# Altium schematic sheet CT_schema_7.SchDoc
size 391 x 238 mm
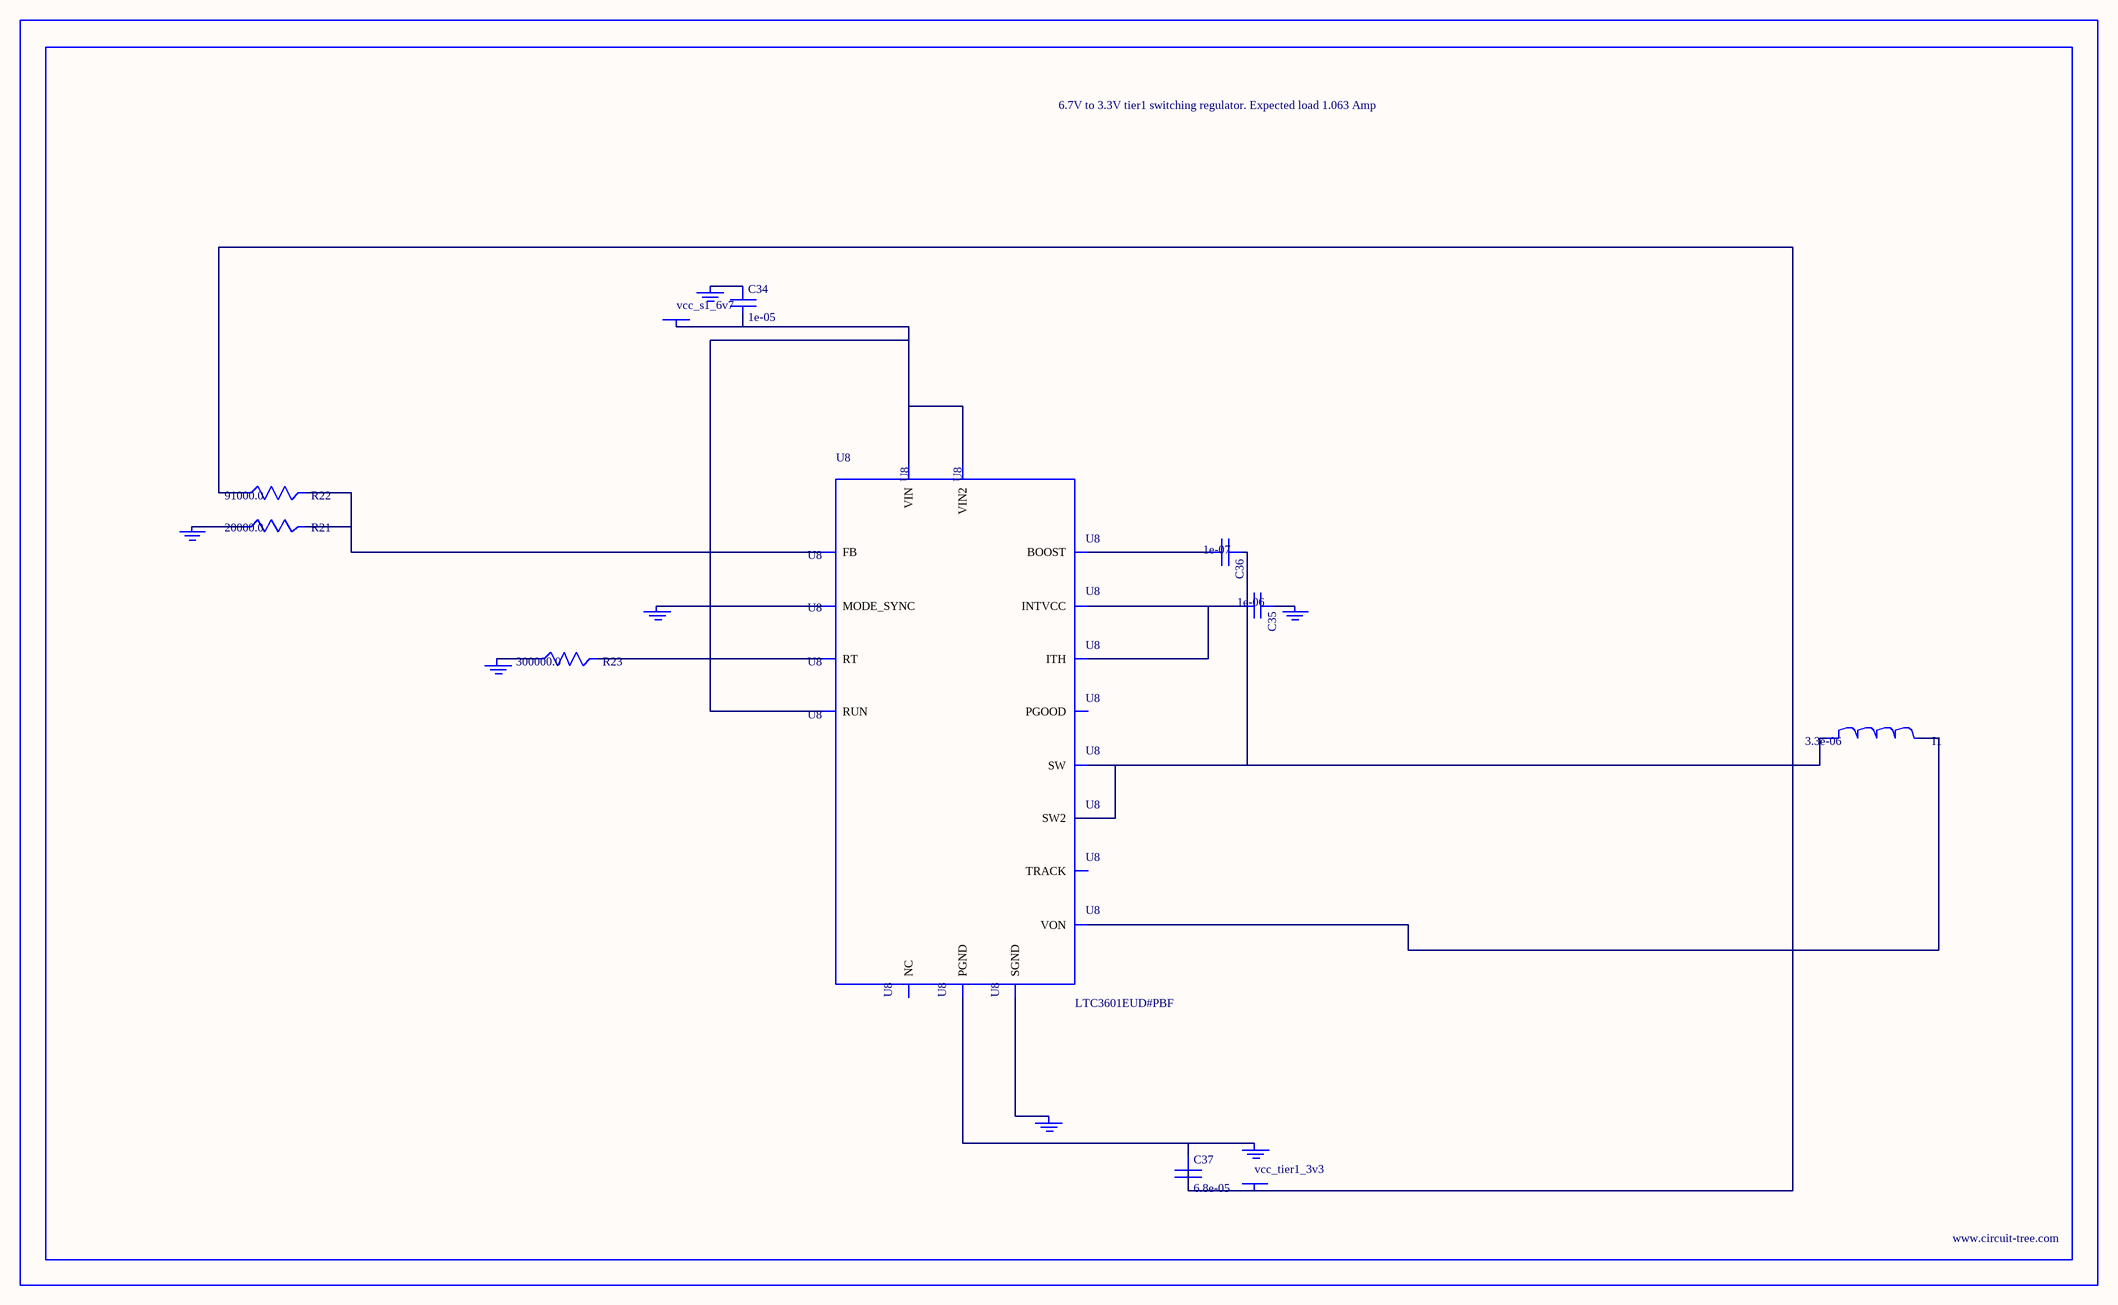
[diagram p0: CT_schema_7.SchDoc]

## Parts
BORDER6  (no value)
C34  1e-05  [C0805]
C35  1e-06  [C0603]
C36  1e-07  [C0402]
C37  6.8e-05  [2220]
GND_INSTANCE_6_0  (no value)
GND_INSTANCE_6_1  (no value)
GND_INSTANCE_6_2  (no value)
GND_INSTANCE_6_3  (no value)
GND_INSTANCE_6_4  (no value)
GND_INSTANCE_6_5  (no value)
GND_INSTANCE_6_6  (no value)
I1  3.3e-06  [WE-HCI_7030/7040/7050]
POWER_INSTANCE_6_0  vcc_s1_6v7
POWER_INSTANCE_6_1  vcc_tier1_3v3
R21  20000.0  [R0603]
R22  91000.0  [R0603]
R23  300000.0  [R0603]
U8  LTC3601EUD#PBF  [QFN-16_EP]

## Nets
NetC34_1: C34.1 GND_INSTANCE_6_5.0(GND)
NetC34_2: C34.2 POWER_INSTANCE_6_0.0(PWR) U8.14(RUN) U8.15(VIN) U8.16(VIN2)
NetC35_1: C35.1 GND_INSTANCE_6_1.0(GND)
NetC35_2: C35.2 U8.7(INTVCC) U8.12(ITH)
NetC36_1: C36.1 I1.1 U8.3(SW) U8.4(SW2)
NetC36_2: C36.2 U8.6(BOOST)
NetC37_1: C37.1 GND_INSTANCE_6_6.0(GND) U8.17(PGND)
NetC37_2: C37.2 I1.2 POWER_INSTANCE_6_1.0(PWR) R22.1 U8.8(VON)
NetGND_INSTANCE_6_0_0: GND_INSTANCE_6_0.0(GND) U8.1(MODE_SYNC)
NetGND_INSTANCE_6_2_0: GND_INSTANCE_6_2.0(GND) U8.9(SGND)
NetGND_INSTANCE_6_3_0: GND_INSTANCE_6_3.0(GND) R23.1
NetGND_INSTANCE_6_4_0: GND_INSTANCE_6_4.0(GND) R21.1
NetR21_2: R21.2 R22.2 U8.11(FB)
NetR23_2: R23.2 U8.10(RT)

Not connected (* = marked no-connect by the designer): U8 2(PGOOD) 5(NC) 13(TRACK)

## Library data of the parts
BORDER6 = BORDER_PAGE6
C34 = C0805C106K8RACTU
C35 = C0603C105K3RACTU
C36 = C0402C104K3RACTU
C37 = C5750X5R1A686M
GND_INSTANCE_6_0-GND_INSTANCE_6_6 = GND
I1 = 744314330
POWER_INSTANCE_6_0 POWER_INSTANCE_6_1 = PWR
R21 = RC0603JR-0720KL
R22 = RC0603JR-0791KL
R23 = RC0603JR-07300KL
